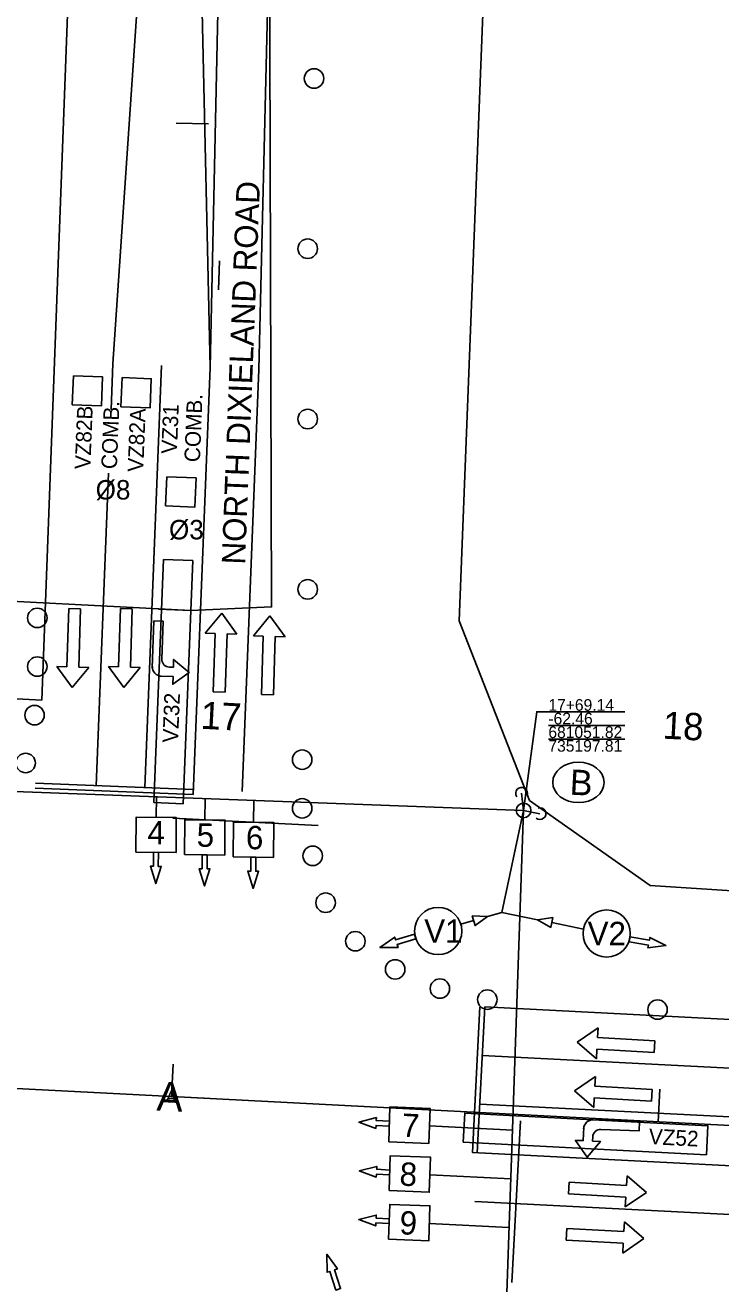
# Model space of a CAD drawing. Extents: x 679444 to 687671, y 733868 to 736107.
# Drawn here: x 680949.5 to 681092.3, y 735100.5 to 735359.2 of the extents above; entities that cross this region are included whole.
import ezdxf

# ---------------------------------------------------------------- set-up
doc = ezdxf.new("R2010")
doc.units = 0
for name, color, linetype in [('$', 7, 'Continuous'), ('090338 Base_Design base 1-1 - R_Horz Alg', 7, 'Continuous'), ('Clipping Boundary', 7, 'Continuous'), ('MOT Stage 1', 7, 'Continuous'), ('MOT Stage 1 Lanes', 7, 'Continuous'), ('R_Horz Alg', 7, 'Continuous'), ('R_Horz Alg Annot', 7, 'Continuous'), ('R_Horz Alg Station', 7, 'Continuous'), ('RW-EX', 7, 'Continuous'), ('SIGNAL-EX', 7, 'Continuous'), ('SIGNAL-PLAN VIEW LABLES', 7, 'Continuous'), ('TITEXT', 7, 'Continuous'), ('Video-Zones-pr', 7, 'Continuous')]:
    doc.layers.add(name, color=color, linetype=linetype)

# ---------------------------------------------------------------- blocks, each defined once
blk = doc.blocks.new('BAREL_1503')
at = {"layer": 'MOT Stage 1'}
blk.add_circle((0, 0.01), 2.88, dxfattribs=at)
blk = doc.blocks.new('SARROW_170')
at = {"layer": 'MOT Stage 1'}
for p, q in [((0, 0), (-6, 0)), ((0, -29.42), (0, 0)), ((-6, -29.42), (-6, 0)), ((-6, -29.42), (-11, -29.42)), ((-3, -39.81), (-11, -29.42)), ((5, -29.42), (-3, -39.81)), ((5, -29.42), (0, -29.42))]:
    blk.add_line(p, q, dxfattribs=at)
blk = doc.blocks.new('SARROW_171')
at = {"layer": 'MOT Stage 1'}
for p, q in [((-6, -29.42), (-6, 0)), ((0, 0), (-6, 0)), ((0, -29.42), (0, 0)), ((-6, -29.42), (-11, -29.42)), ((-3, -39.81), (-11, -29.42)), ((5, -29.42), (-3, -39.81)), ((5, -29.42), (0, -29.42))]:
    blk.add_line(p, q, dxfattribs=at)
blk = doc.blocks.new('SARROW_173')
at = {"layer": 'MOT Stage 1'}
for p, q in [((0, 0), (-6, 0)), ((0, -29.42), (0, 0)), ((-6, -29.42), (-6, 0)), ((-6, -29.42), (-11, -29.42)), ((-3, -39.81), (-11, -29.42)), ((5, -29.42), (-3, -39.81)), ((5, -29.42), (0, -29.42))]:
    blk.add_line(p, q, dxfattribs=at)
blk = doc.blocks.new('SARROW_174')
at = {"layer": 'MOT Stage 1'}
for p, q in [((-6, -29.42), (-6, 0)), ((0, 0), (-6, 0)), ((0, -29.42), (0, 0)), ((-6, -29.42), (-11, -29.42)), ((-3, -39.81), (-11, -29.42)), ((5, -29.42), (-3, -39.81)), ((5, -29.42), (0, -29.42))]:
    blk.add_line(p, q, dxfattribs=at)
blk = doc.blocks.new('SARROW_175')
at = {"layer": 'MOT Stage 1'}
for p, q in [((-6, -29.42), (-6, 0)), ((0, 0), (-6, 0)), ((0, -29.42), (0, 0)), ((-6, -29.42), (-11, -29.42)), ((-3, -39.81), (-11, -29.42)), ((5, -29.42), (-3, -39.81)), ((5, -29.42), (0, -29.42))]:
    blk.add_line(p, q, dxfattribs=at)
blk = doc.blocks.new('SARROW_176')
at = {"layer": 'MOT Stage 1'}
for p, q in [((-6, -29.42), (-6, 0)), ((0, 0), (-6, 0)), ((0, -29.42), (0, 0)), ((-6, -29.42), (-11, -29.42)), ((-3, -39.81), (-11, -29.42)), ((5, -29.42), (-3, -39.81)), ((5, -29.42), (0, -29.42))]:
    blk.add_line(p, q, dxfattribs=at)
blk = doc.blocks.new('BAREL_1543')
at = {"layer": 'MOT Stage 1'}
blk.add_circle((0, 0.01), 2.88, dxfattribs=at)
blk = doc.blocks.new('BAREL_1544')
at = {"layer": 'MOT Stage 1'}
blk.add_circle((0, 0.01), 2.88, dxfattribs=at)
blk = doc.blocks.new('BAREL_1545')
at = {"layer": 'MOT Stage 1'}
blk.add_circle((0, 0.01), 2.88, dxfattribs=at)
blk = doc.blocks.new('BAREL_1546')
at = {"layer": 'MOT Stage 1'}
blk.add_circle((0, 0.01), 2.88, dxfattribs=at)
blk = doc.blocks.new('BAREL_1547')
at = {"layer": 'MOT Stage 1'}
blk.add_circle((0, 0.01), 2.88, dxfattribs=at)
blk = doc.blocks.new('BAREL_1548')
at = {"layer": 'MOT Stage 1'}
blk.add_circle((0, 0.01), 2.88, dxfattribs=at)
blk = doc.blocks.new('BAREL_1549')
at = {"layer": 'MOT Stage 1'}
blk.add_circle((0, 0.01), 2.88, dxfattribs=at)
blk = doc.blocks.new('BAREL_1550')
at = {"layer": 'MOT Stage 1'}
blk.add_circle((0, 0.01), 2.88, dxfattribs=at)
blk = doc.blocks.new('BAREL_1551')
at = {"layer": 'MOT Stage 1'}
blk.add_circle((0, 0.01), 2.88, dxfattribs=at)
blk = doc.blocks.new('BAREL_1552')
at = {"layer": 'MOT Stage 1'}
blk.add_circle((0, 0.01), 2.88, dxfattribs=at)
blk = doc.blocks.new('BAREL_1553')
at = {"layer": 'MOT Stage 1'}
blk.add_circle((0, 0.01), 2.88, dxfattribs=at)
blk = doc.blocks.new('BAREL_1554')
at = {"layer": 'MOT Stage 1'}
blk.add_circle((0, 0.01), 2.88, dxfattribs=at)
blk = doc.blocks.new('SARROW_180')
at = {"layer": 'MOT Stage 1'}
for p, q in [((-6, -29.42), (-6, 0)), ((0, 0), (-6, 0)), ((0, -29.42), (0, 0)), ((-6, -29.42), (-11, -29.42)), ((-3, -39.81), (-11, -29.42)), ((5, -29.42), (-3, -39.81)), ((5, -29.42), (0, -29.42))]:
    blk.add_line(p, q, dxfattribs=at)
blk = doc.blocks.new('SARROW_183')
at = {"layer": 'MOT Stage 1'}
for p, q in [((-6, -29.42), (-6, 0)), ((0, 0), (-6, 0)), ((0, -29.42), (0, 0)), ((-6, -29.42), (-11, -29.42)), ((-3, -39.81), (-11, -29.42)), ((5, -29.42), (-3, -39.81)), ((5, -29.42), (0, -29.42))]:
    blk.add_line(p, q, dxfattribs=at)
blk = doc.blocks.new('BAREL_1579')
at = {"layer": 'MOT Stage 1'}
blk.add_circle((0, 0.01), 2.88, dxfattribs=at)
blk = doc.blocks.new('BAREL_1580')
at = {"layer": 'MOT Stage 1'}
blk.add_circle((0, 0.01), 2.88, dxfattribs=at)
blk = doc.blocks.new('BAREL_1581')
at = {"layer": 'MOT Stage 1'}
blk.add_circle((0, 0.01), 2.88, dxfattribs=at)
blk = doc.blocks.new('BAREL_1582')
at = {"layer": 'MOT Stage 1'}
blk.add_circle((0, 0.01), 2.88, dxfattribs=at)
blk = doc.blocks.new('POINT_DISPLAY')
blk.add_line((0, 0), (0, 0))

msp = doc.modelspace()

# ---------------------------------------------------------------- linework, layer by layer
at = {"layer": '$'}
for p, q in [((680920.66, 735202.66), (681051.82, 735197.81)), ((681051.82, 735197.81), (681047.67, 735079.32))]:
    msp.add_line(p, q, dxfattribs=at)
for points in [[(681051.39, 735201.34), (681051.82, 735197.81)], [(681055.18, 735197.14), (681051.82, 735197.81)]]:
    msp.add_lwpolyline(points, dxfattribs=at)
msp.add_circle((681051.82, 735197.81), 1.5, dxfattribs=at)
for centre, start, end in [((681051.39, 735201.34), 336.857, 216.857), ((681055.18, 735197.14), 228.7994, 108.7994)]:
    msp.add_arc(centre, 1.2, start, end, dxfattribs=at)
at = {"layer": 'Clipping Boundary'}
msp.add_lwpolyline([(680983.49, 735238.92), (680930.7, 735241.61), (680945.08, 735370.96), (680954.81, 735458.55), (680999.35, 735471.11), (681000.07, 735239.64)], close=True, dxfattribs=at)
at = {"layer": 'MOT Stage 1'}
for points in [[(680975.9, 735236.75), (680975.59, 735227.05), (680975.6, 735227.37)], [(680977.55, 735228.89), (680977.8, 735236.69), (680975.9, 735236.75)], [(680977.44, 735225.4), (680977.12, 735225.41), (680979.85, 735225.33), (680979.8, 735223.74), (680983.18, 735226.17), (680979.97, 735228.82), (680979.92, 735227.23), (680979.09, 735227.26)], [(681075.58, 735133.87), (681065.81, 735134.24), (681066.13, 735134.22)], [(681067.66, 735132.25), (681075.51, 735131.95), (681075.58, 735133.87)], [(681064.14, 735132.38), (681064.15, 735132.7), (681064.05, 735129.95), (681062.45, 735130.01), (681064.89, 735126.59), (681067.57, 735129.81), (681065.97, 735129.87), (681066, 735130.71)]]:
    msp.add_lwpolyline(points, dxfattribs=at)
for centre, radius, start, end in [((680977.5, 735227.31), 1.9, 178.1773, 268.1773), ((680979.14, 735228.84), 1.59, 178.1773, 268.1773), ((681066.06, 735132.31), 1.92, 87.8614, 177.8614), ((681067.6, 735130.65), 1.6, 87.8614, 177.8614)]:
    msp.add_arc(centre, radius, start, end, dxfattribs=at)
at = {"layer": 'MOT Stage 1 Lanes'}
for p, q in [((680967.48, 735289.6), (680982.89, 735514.32)), ((680987.46, 735288.81), (680992.34, 735513.78)), ((681002.99, 735513.22), (680997.45, 735288.41)), ((680987.46, 735288.81), (680984.91, 735401.49)), ((680967.11, 735280.21), (680967.48, 735289.6)), ((680974.05, 735202.5), (680977.47, 735289.2)), ((680994.03, 735201.71), (680997.45, 735288.41)), ((680964.06, 735202.89), (680966.59, 735267.1)), ((681043.86, 735157.43), (681230.33, 735147.83)), ((681043.34, 735147.44), (681106.86, 735144.17)), ((681042.83, 735137.46), (681229.3, 735127.86)), ((681041.8, 735117.48), (681228.28, 735107.88))]:
    msp.add_line(p, q, dxfattribs=at)
for points in [[(680951.55, 735202.38), (680984, 735201.1), (680987.46, 735288.81)], [(680951.59, 735203.38), (680984.04, 735202.1)], [(681042.86, 735157.48), (681041.31, 735127.52), (681228.79, 735117.87)], [(681043.86, 735157.43), (681042.31, 735127.47)]]:
    msp.add_lwpolyline(points, dxfattribs=at)
at = {"layer": 'R_Horz Alg Annot'}
for p, q in [((681056.9, 735218.08), (681072.59, 735218.08)), ((681056.9, 735215.28), (681072.59, 735215.28)), ((681056.9, 735212.48), (681072.59, 735212.48))]:
    msp.add_line(p, q, dxfattribs=at)
msp.add_lwpolyline([(681051.82, 735197.81), (681054.5, 735218.08), (681056.9, 735218.08)], dxfattribs=at)
at = {"layer": 'R_Horz Alg Station'}
for p, q in [((680355.32, 735171.01), (680979.55, 735139)), ((680979.55, 735139), (682304.99, 735070.5))]:
    msp.add_line(p, q, dxfattribs=at)
for points in [[(680980.48, 735339.05), (680987.14, 735338.86)], [(680976.83, 735239.19), (680983.49, 735238.92)], [(680979.89, 735145.66), (680979.55, 735139)], [(680972.89, 735139.34), (680986.21, 735138.66)], [(681079.76, 735140.5), (681079.41, 735133.84)]]:
    msp.add_lwpolyline(points, dxfattribs=at)
at = {"layer": 'RW-EX'}
for p, q in [((680952.9, 735220.48), (680961.67, 735453.52)), ((681046.38, 735436.08), (681038.61, 735236.76)), ((681038.61, 735236.76), (681053.04, 735199.88)), ((680943.65, 735220.95), (680952.9, 735220.48))]:
    msp.add_line(p, q, dxfattribs=at)
msp.add_lwpolyline([(681053.04, 735199.88), (681077.83, 735182.39), (681128.41, 735179.07), (681183.11, 735183.4), (681262.95, 735179.36), (681262.33, 735164.44), (681417.02, 735156.45)], dxfattribs=at)
at = {"layer": 'SIGNAL-EX'}
for p, q in [((681009.63, 735194.69), (680979.83, 735196.25)), ((681049.43, 735100.83), (681051.18, 735134.05))]:
    msp.add_line(p, q, dxfattribs=at)
at = {"layer": 'SIGNAL-PLAN VIEW LABLES'}
for p, q in [((680975.83, 735189.2), (680975.82, 735186.32)), ((680976.84, 735189.19), (680975.83, 735189.2)), ((680976.82, 735186.31), (680976.84, 735189.19)), ((680985.83, 735188.7), (680985.81, 735185.82)), ((680986.84, 735188.69), (680985.83, 735188.7)), ((680986.82, 735185.81), (680986.84, 735188.69)), ((680995.83, 735188.21), (680995.81, 735185.32)), ((680996.84, 735188.19), (680995.83, 735188.21)), ((680996.82, 735185.31), (680996.84, 735188.19)), ((680975.82, 735186.32), (680975.21, 735186.32)), ((680975.21, 735186.32), (680976.3, 735182.77)), ((680976.3, 735182.77), (680977.43, 735186.31)), ((680977.43, 735186.31), (680976.82, 735186.31)), ((680985.81, 735185.82), (680985.21, 735185.82)), ((680985.21, 735185.82), (680986.29, 735182.28)), ((680986.29, 735182.28), (680987.42, 735185.81)), ((680987.42, 735185.81), (680986.82, 735185.81)), ((680995.81, 735185.32), (680995.2, 735185.33)), ((680995.2, 735185.33), (680996.29, 735181.78)), ((680996.29, 735181.78), (680997.42, 735185.31)), ((680997.42, 735185.31), (680996.82, 735185.31)), ((681021.61, 735134.68), (681018.02, 735133.75)), ((681018.02, 735133.75), (681021.49, 735132.47)), ((681021.58, 735134.08), (681021.61, 735134.68)), ((681024.27, 735133.94), (681021.58, 735134.08)), ((681024.23, 735132.93), (681024.27, 735133.94)), ((681021.49, 735132.47), (681021.53, 735133.07)), ((681021.53, 735133.07), (681024.23, 735132.93)), ((681021.68, 735124.66), (681018.09, 735123.74)), ((681018.09, 735123.74), (681021.57, 735122.45)), ((681021.57, 735122.45), (681021.6, 735123.05)), ((681021.6, 735123.05), (681024.31, 735122.91)), ((681021.65, 735124.06), (681021.68, 735124.66)), ((681024.35, 735123.92), (681021.65, 735124.06)), ((681024.31, 735122.91), (681024.35, 735123.92)), ((681021.56, 735114.66), (681017.97, 735113.73)), ((681017.97, 735113.73), (681021.45, 735112.44)), ((681021.45, 735112.44), (681021.48, 735113.05)), ((681021.48, 735113.05), (681024.19, 735112.91)), ((681021.53, 735114.05), (681021.56, 735114.66)), ((681024.23, 735113.91), (681021.53, 735114.05)), ((681024.19, 735112.91), (681024.23, 735113.91))]:
    msp.add_line(p, q, dxfattribs=at)
for points in [[(680976.42, 735200.6), (680976.39, 735196.37)], [(680986.41, 735200.23), (680986.38, 735195.87)], [(680996.41, 735199.86), (680996.38, 735195.37)], [(681051.82, 735197.81), (681047.33, 735176.83)], [(680975.83, 735189.2), (680975.82, 735186.32), (680975.21, 735186.32), (680976.3, 735182.77), (680977.43, 735186.31), (680976.82, 735186.31), (680976.84, 735189.19)], [(680985.83, 735188.7), (680985.81, 735185.82), (680985.21, 735185.82), (680986.29, 735182.28), (680987.42, 735185.81), (680986.82, 735185.81), (680986.84, 735188.69)], [(680995.83, 735188.21), (680995.81, 735185.32), (680995.2, 735185.33), (680996.29, 735181.78), (680997.42, 735185.31), (680996.82, 735185.31), (680996.84, 735188.19)], [(681041.56, 735175.16), (681038.92, 735174.42)], [(681047.33, 735176.83), (681044.41, 735175.99)], [(681047.33, 735176.86), (681054.7, 735175.35)], [(681025.54, 735171.2), (681025.36, 735171.78), (681022.32, 735169.66), (681026.03, 735169.66), (681025.85, 735170.24), (681029.69, 735171.45), (681029.39, 735172.41), (681025.54, 735171.2)], [(681029.39, 735172.41), (681025.54, 735171.2), (681025.36, 735171.78), (681022.32, 735169.66), (681026.03, 735169.66), (681025.85, 735170.24), (681029.69, 735171.45)], [(681057.6, 735174.75), (681064.09, 735173.42)], [(681077.45, 735170.14), (681077.35, 735169.54), (681081.03, 735170.03), (681077.73, 735171.73), (681077.63, 735171.13), (681073.65, 735171.82), (681073.48, 735170.83), (681077.45, 735170.14)], [(681073.48, 735170.83), (681077.45, 735170.14), (681077.35, 735169.54), (681081.03, 735170.03), (681077.73, 735171.73), (681077.63, 735171.13), (681073.65, 735171.82)], [(681024.27, 735133.94), (681021.58, 735134.08), (681021.61, 735134.68), (681018.02, 735133.75), (681021.49, 735132.47), (681021.53, 735133.07), (681024.23, 735132.93)], [(681049.52, 735132.11), (681032.5, 735132.98)], [(681024.35, 735123.92), (681021.65, 735124.06), (681021.68, 735124.66), (681018.09, 735123.74), (681021.57, 735122.45), (681021.6, 735123.05), (681024.31, 735122.91)], [(681049.17, 735122.11), (681032.58, 735122.96)], [(681024.23, 735113.91), (681021.53, 735114.05), (681021.56, 735114.66), (681017.97, 735113.73), (681021.45, 735112.44), (681021.48, 735113.05), (681024.19, 735112.91)], [(681048.81, 735112.12), (681032.46, 735112.95)], [(681013, 735103.4), (681013.58, 735103.58), (681011.43, 735106.61), (681011.47, 735102.9), (681012.04, 735103.09), (681013.28, 735099.25), (681014.24, 735099.56), (681013, 735103.4)], [(681014.24, 735099.56), (681013, 735103.4), (681013.58, 735103.58), (681011.43, 735106.61), (681011.47, 735102.9), (681012.04, 735103.09), (681013.28, 735099.25)]]:
    msp.add_lwpolyline(points, dxfattribs=at)
for points in [[(680972.21, 735189.26), (680972.26, 735196.39), (680980.52, 735196.34), (680980.47, 735189.13)], [(680982.21, 735188.76), (680982.25, 735195.9), (680990.51, 735195.84), (680990.47, 735188.64)], [(680992.2, 735188.26), (680992.25, 735195.4), (681000.51, 735195.34), (681000.46, 735188.14)], [(681044.41, 735175.99), (681041.85, 735174.16), (681041.28, 735176.16)], [(681054.7, 735175.35), (681057.81, 735175.8), (681057.39, 735173.76)], [(681024.12, 735129.74), (681024.37, 735136.87), (681032.63, 735136.58), (681032.38, 735129.38)], [(681024.2, 735119.72), (681024.45, 735126.85), (681032.7, 735126.56), (681032.45, 735119.36)], [(681024.08, 735109.71), (681024.33, 735116.84), (681032.58, 735116.56), (681032.33, 735109.36)]]:
    msp.add_lwpolyline(points, close=True, dxfattribs=at)
for centre in [(681034.28, 735173.02), (681068.86, 735172.52)]:
    msp.add_circle(centre, 4.85, dxfattribs=at)
msp.add_ellipse((681063.07, 735203.57), major_axis=(-5.27, 0), ratio=0.790685, dxfattribs=at)
at = {"layer": 'Video-Zones-pr'}
for points in [[(680989.17, 735304.75), (680989.4, 735310.75)], [(680959.38, 735287.14), (680965.37, 735286.9), (680965.14, 735280.91), (680959.14, 735281.15)], [(680959.14, 735281.15), (680959.38, 735287.14)], [(680969.37, 735286.75), (680975.36, 735286.51), (680975.13, 735280.52), (680969.13, 735280.75)], [(680969.13, 735280.75), (680969.37, 735286.75)], [(680978.57, 735266.37), (680984.57, 735266.13), (680984.33, 735260.14), (680978.33, 735260.37)], [(680978.33, 735260.37), (680978.57, 735266.37)]]:
    msp.add_lwpolyline(points, dxfattribs=at)
for points in [[(680977.9, 735249.38), (680975.93, 735199.42), (680981.92, 735199.18), (680983.9, 735249.14)], [(681039.42, 735129.62), (681089.35, 735127.04), (681089.66, 735133.03), (681039.73, 735135.61)]]:
    msp.add_lwpolyline(points, close=True, dxfattribs=at)

# ---------------------------------------------------------------- block references
at = {"layer": '$', "rotation": 177.88367850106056}
msp.add_blockref('POINT_DISPLAY', (681056.31, 735197.64), dxfattribs=at)
at = {"layer": 'MOT Stage 1'}
for name, p, xscale, yscale, rotation in [('BAREL_1554', (681008.8, 735348.2), 0.6945420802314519, 0.6945420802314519, 87.04179557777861), ('BAREL_1553', (681007.5, 735313.23), 0.6945420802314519, 0.6945420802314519, 87.04179557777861), ('BAREL_1552', (681007.5, 735278.23), 0.6945420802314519, 0.6945420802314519, 87.04179557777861), ('BAREL_1551', (681007.5, 735243.23), 0.6945420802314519, 0.6945420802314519, 87.04179557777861), ('BAREL_1582', (680951.98, 735237.37), 0.6945420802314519, 0.6945420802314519, 83.20696384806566), ('SARROW_170', (680960.87, 735239.23), 0.4075873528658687, 0.4075873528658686, -1.8227149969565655), ('SARROW_180', (680971.47, 735239.23), 0.4075873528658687, 0.4075873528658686, -1.8227149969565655), ('SARROW_171', (680988.1, 735222.16), 0.4075873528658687, 0.4075873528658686, 178.17728500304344), ('SARROW_183', (680998, 735221.63), 0.4075873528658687, 0.4075873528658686, 178.17728500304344), ('BAREL_1581', (680951.98, 735227.37), 0.6945420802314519, 0.6945420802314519, 83.20696384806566), ('BAREL_1580', (680951.42, 735217.38), 0.6945420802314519, 0.6945420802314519, 83.20696384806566), ('BAREL_1579', (680949.59, 735207.55), 0.6945420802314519, 0.6945420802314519, 83.20696384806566), ('BAREL_1550', (681006.36, 735208.24), 0.6945420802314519, 0.6945420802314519, 87.04179557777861), ('BAREL_1549', (681006.36, 735198.24), 0.6945420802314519, 0.6945420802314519, 87.04179557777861), ('BAREL_1548', (681008.53, 735188.48), 0.6945420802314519, 0.6945420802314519, 87.04179557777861), ('BAREL_1547', (681011.18, 735178.84), 0.6945420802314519, 0.6945420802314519, 87.04179557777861), ('BAREL_1546', (681017.29, 735170.93), 0.6945420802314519, 0.6945420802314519, 87.04179557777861), ('BAREL_1545', (681025.45, 735165.14), 0.6945420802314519, 0.6945420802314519, 87.04179557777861), ('BAREL_1544', (681034.64, 735161.2), 0.6945420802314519, 0.6945420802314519, 87.04179557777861), ('BAREL_1543', (681044.38, 735158.93), 0.6945420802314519, 0.6945420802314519, 87.04179557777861), ('BAREL_1503', (681079.32, 735156.89), 0.6945420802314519, 0.6945420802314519, 87.04179557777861), ('SARROW_174', (681078.63, 735148.07), 0.39999999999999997, 0.39999999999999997, -93.21769625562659), ('SARROW_175', (681078.07, 735138.09), 0.39999999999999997, 0.39999999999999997, -93.21769625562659), ('SARROW_173', (681061.06, 735119), 0.40000000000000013, -0.40000000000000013, -93.21769625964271), ('SARROW_176', (681060.53, 735109.52), 0.40000000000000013, -0.40000000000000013, -93.21769625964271)]:
    msp.add_blockref(name, p, dxfattribs=dict(at, xscale=xscale, yscale=yscale, rotation=rotation))

# ---------------------------------------------------------------- texts
at = {"layer": '$'}
for s, height, rotation, p in [('NORTH DIXIELAND ROAD', 4.8, 87.7567, (680994.63, 735248.27)), ('COMB.', 3.2, 87.7397, (680968.3, 735267.89)), ('VZ31', 3.2, 87.7397, (680980.63, 735271.03)), ('COMB.', 3.2, 87.7397, (680985.36, 735269.32)), ('VZ82B', 3.2, 87.7397, (680962.86, 735267.86)), ('VZ82A', 3.2, 87.7397, (680973.72, 735267.31)), ('VZ32', 3.2, 87.7397, (680980.87, 735211.67)), ('17', 5.6, 357.065, (680985.41, 735214.6)), ('18', 5.6, 357.0415, (681080.28, 735212.57)), ('VZ52', 3.2, 357.065, (681077.44, 735129.25))]:
    msp.add_text(s, height=height, rotation=rotation, dxfattribs=at).set_placement(p)
at = {"layer": '090338 Base_Design base 1-1 - R_Horz Alg'}
msp.add_text('A', height=2.4, rotation=357.0533, dxfattribs=at).set_placement((680978.3, 735137.87))
at = {"layer": 'R_Horz Alg'}
msp.add_text('A', height=6, rotation=357.0533, dxfattribs=at).set_placement((680976.4, 735136.16))
at = {"layer": 'R_Horz Alg Annot'}
for s, p in [('17+69.14', (681056.9, 735218.28)), ('-62.46', (681056.9, 735215.48)), ('681051.82', (681056.9, 735212.68)), ('735197.81', (681056.9, 735209.88))]:
    msp.add_text(s, height=2.4, dxfattribs=at).set_placement(p)
at = {"layer": 'SIGNAL-PLAN VIEW LABLES'}
for s, height, rotation, p in [('B', 5.2, 357.0414, (681061.2, 735201.06)), ('4', 4.8, 359.5982, (680974.58, 735190.84)), ('5', 4.8, 359.5982, (680984.69, 735190.34)), ('6', 4.8, 359.5982, (680994.8, 735189.84)), ('7', 4.8, 357.0414, (681026.71, 735130.76)), ('8', 4.8, 357.0414, (681026.26, 735120.75)), ('9', 4.8, 357.0414, (681026.25, 735110.74))]:
    msp.add_text(s, height=height, rotation=rotation, dxfattribs=at).set_placement(p)
for s, p in [('V1', (681031.42, 735170.62)), ('V2', (681064.97, 735170.12))]:
    msp.add_text(s, height=4.8, dxfattribs=at).set_placement(p)
at = {"layer": 'TITEXT'}
for s, p in [('%%C8', (680963.96, 735261.69)), ('%%C3', (680979.02, 735253.5))]:
    msp.add_text(s, height=4, dxfattribs=at).set_placement(p)

doc.saveas('drawing.dxf')
